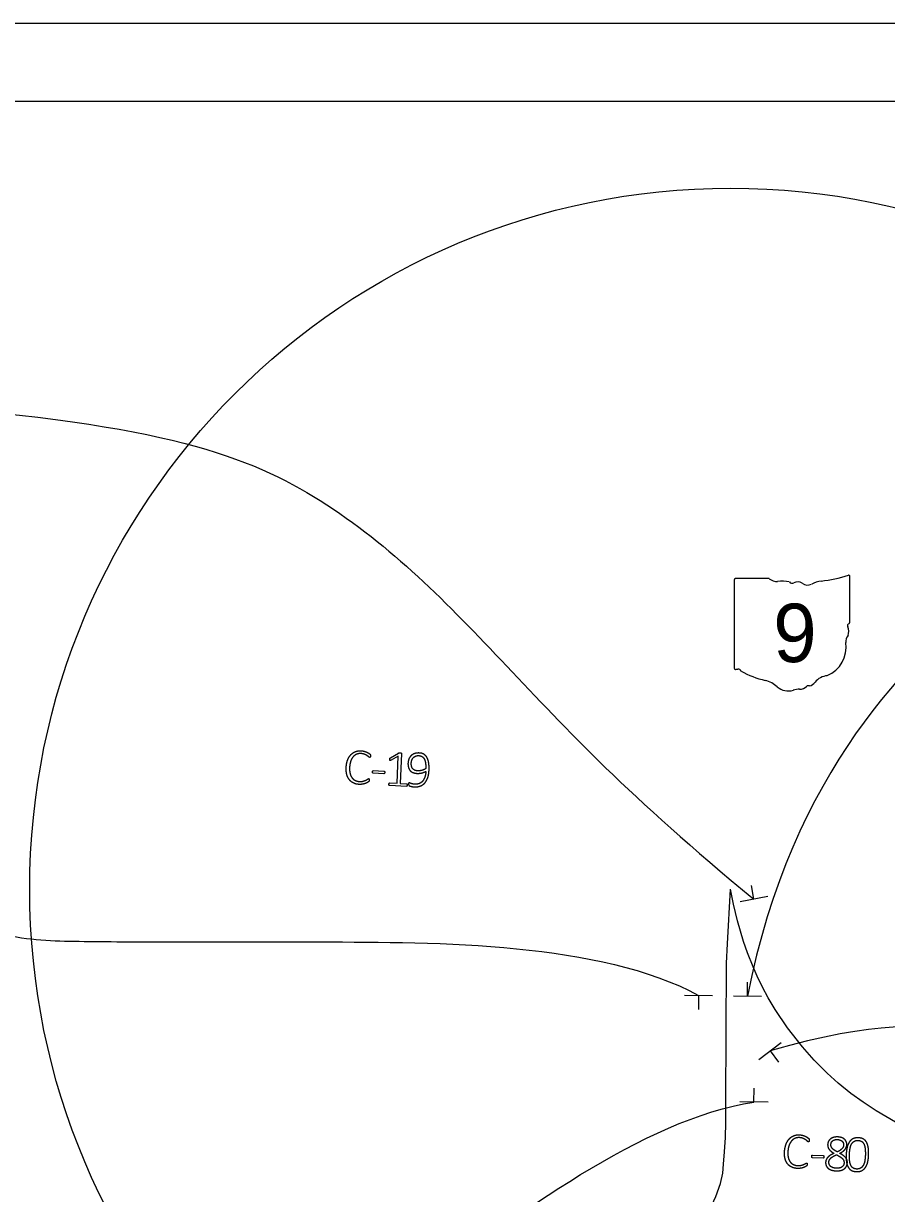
# Model space of a CAD drawing. Extents: x -202 to 1556, y 0 to 676.
# Drawn here: x 412.8 to 523.6, y 289.7 to 440 of the extents above; entities that cross this region are included whole.
import ezdxf

# ---------------------------------------------------------------- set-up
doc = ezdxf.new("R2010")
doc.units = 0
for name, color, linetype in [('Default', 7, 'Continuous'), ('GM_X_City_Street', 7, 'Continuous'), ('GM_X_Minor_Lake', 7, 'Continuous'), ('GM_X_State_Location', 7, 'Continuous'), ('SH_Border', 7, 'Continuous'), ('SH_Cut_Line', 7, 'Continuous'), ('SH_Data', 7, 'Continuous')]:
    doc.layers.add(name, color=color, linetype=linetype)

msp = doc.modelspace()

# ---------------------------------------------------------------- linework, layer by layer
at = {"layer": 'Default'}
for p, q in [((514.1, 294.69), (515.48, 294.62)), ((518.1, 295.99), (518.1, 295.99)), ((520.89, 294.67), (520.89, 294.67)), ((521.31, 294.69), (521.31, 294.69)), ((513.41, 293.48), (513.41, 293.48)), ((515.46, 294.3), (514.09, 294.36)), ((515.57, 294.46), (515.57, 294.46)), ((518.16, 293.69), (518.16, 293.69)), ((518.58, 293.73), (518.58, 293.73))]:
    msp.add_line(p, q, dxfattribs=at)
for points in [[(453.85, 253.83), (455.86, 255.51), (463.64, 260.9), (478.31, 270.7), (483.79, 274.45), (492.41, 280.21), (495.65, 282.4), (496.96, 283.36), (498.18, 284.37), (499.83, 286.07), (500.62, 287.27), (501.16, 288.25), (501.69, 289.38), (502.3, 291.03), (502.57, 292.38), (502.68, 293.54), (502.8, 295.12), (502.92, 296.94), (502.99, 298.87), (502.99, 301.52), (503.08, 319.32), (503.18, 321.83), (503.59, 328.84)], [(579.61, 280.65), (575.86, 281.89), (555.1, 288.55), (531.8, 295.84), (527.22, 297.75), (524.76, 298.93), (522.29, 300.36), (520.6, 301.48), (519.03, 302.61), (517.4, 303.94), (515.97, 305.23), (514.31, 306.9), (512.8, 308.58), (510.9, 311.04), (509.31, 313.39), (508.43, 314.89), (507.69, 316.25), (506.99, 317.65), (506.47, 318.86), (505.75, 320.66), (505.24, 322.11), (504.47, 324.76), (503.95, 326.92), (503.59, 328.84)]]:
    msp.add_lwpolyline(points, dxfattribs=at)
for points in [[(510.52, 295.25), (510.57, 295.76), (510.74, 296.16)], [(510.74, 296.16), (510.9, 296.56), (511.17, 296.82)], [(511.12, 296.01), (510.99, 295.68), (510.95, 295.23)], [(511.45, 296.55), (511.26, 296.34), (511.12, 296.01)], [(511.17, 296.82), (511.43, 297.09), (511.78, 297.21)], [(511.91, 296.86), (511.65, 296.77), (511.45, 296.55)], [(511.78, 297.21), (512.12, 297.33), (512.52, 297.29)], [(512.47, 296.93), (512.17, 296.96), (511.91, 296.86)], [(512.93, 296.82), (512.74, 296.9), (512.47, 296.93)], [(512.52, 297.29), (512.71, 297.27), (512.89, 297.22)], [(512.89, 297.22), (513.06, 297.17), (513.21, 297.1)], [(513.25, 296.64), (513.12, 296.73), (512.93, 296.82)], [(513.21, 297.1), (513.35, 297.03), (513.46, 296.94)], [(513.45, 296.47), (513.38, 296.54), (513.25, 296.64)], [(513.57, 296.39), (513.53, 296.39), (513.45, 296.47)], [(513.46, 296.94), (513.58, 296.86), (513.62, 296.81)], [(513.62, 296.4), (513.6, 296.39), (513.57, 296.39)], [(513.62, 296.81), (513.66, 296.76), (513.67, 296.74)], [(513.65, 296.43), (513.63, 296.41), (513.62, 296.4)], [(513.67, 296.49), (513.66, 296.46), (513.65, 296.43)], [(513.67, 296.74), (513.68, 296.72), (513.68, 296.7)], [(513.68, 296.57), (513.68, 296.53), (513.67, 296.49)], [(513.68, 296.7), (513.68, 296.67), (513.68, 296.64)], [(513.68, 296.64), (513.68, 296.61), (513.68, 296.57)], [(516.14, 296.43), (516.06, 296.25), (516.05, 296.04)], [(516.05, 296.04), (516.05, 295.87), (516.09, 295.71)], [(516.39, 296.75), (516.23, 296.61), (516.14, 296.43)], [(516.79, 296.96), (516.55, 296.89), (516.39, 296.75)], [(516.51, 295.79), (516.46, 295.91), (516.47, 296.05)], [(516.47, 296.05), (516.48, 296.36), (516.69, 296.53)], [(516.69, 296.53), (516.91, 296.7), (517.31, 296.69)], [(517.36, 297.02), (517.03, 297.03), (516.79, 296.96)], [(517.31, 296.69), (517.5, 296.68), (517.65, 296.62)], [(517.88, 296.92), (517.66, 297.01), (517.36, 297.02)], [(517.65, 296.62), (517.8, 296.57), (517.9, 296.48)], [(518.25, 296.7), (518.1, 296.83), (517.88, 296.92)], [(517.9, 296.48), (518.01, 296.39), (518.05, 296.27)], [(518.05, 296.27), (518.1, 296.14), (518.1, 295.99)], [(518.45, 296.38), (518.39, 296.56), (518.25, 296.7)], [(518.44, 295.68), (518.5, 295.84), (518.51, 296.02)], [(518.51, 296.02), (518.52, 296.21), (518.45, 296.38)], [(518.81, 296.34), (518.63, 296.06), (518.54, 295.66)], [(519.29, 296.78), (519, 296.63), (518.81, 296.34)], [(518.92, 295.48), (518.97, 295.8), (519.09, 296.05)], [(519.09, 296.05), (519.21, 296.3), (519.42, 296.44)], [(520, 296.91), (519.58, 296.93), (519.29, 296.78)], [(519.42, 296.44), (519.63, 296.59), (519.95, 296.57)], [(519.95, 296.57), (520.13, 296.57), (520.27, 296.51)], [(520.64, 296.75), (520.38, 296.9), (520, 296.91)], [(520.27, 296.51), (520.42, 296.46), (520.53, 296.36)], [(520.53, 296.36), (520.63, 296.25), (520.71, 296.1)], [(521.06, 296.32), (520.9, 296.6), (520.64, 296.75)], [(520.71, 296.1), (520.78, 295.94), (520.83, 295.73)], [(521.27, 295.63), (521.21, 296.03), (521.06, 296.32)], [(510.56, 294.34), (510.47, 294.75), (510.52, 295.25)], [(510.95, 295.23), (510.91, 294.81), (510.97, 294.48)], [(514, 294.53), (514, 294.62), (514.03, 294.66)], [(514.02, 294.4), (513.99, 294.44), (514, 294.53)], [(514.03, 294.66), (514.06, 294.69), (514.1, 294.69)], [(515.48, 294.62), (515.5, 294.62), (515.51, 294.61)], [(515.51, 294.61), (515.53, 294.6), (515.54, 294.58)], [(515.54, 294.58), (515.56, 294.56), (515.56, 294.53)], [(515.56, 294.53), (515.57, 294.5), (515.57, 294.46)], [(516.09, 295.71), (516.14, 295.56), (516.25, 295.42)], [(516.43, 294.7), (516.24, 294.58), (516.1, 294.44)], [(516.25, 295.42), (516.35, 295.28), (516.51, 295.16)], [(516.88, 294.92), (516.63, 294.81), (516.43, 294.7)], [(516.47, 294.32), (516.59, 294.43), (516.77, 294.53)], [(516.65, 295.55), (516.55, 295.67), (516.51, 295.79)], [(516.51, 295.16), (516.67, 295.03), (516.88, 294.92)], [(516.9, 295.33), (516.75, 295.44), (516.65, 295.55)], [(516.77, 294.53), (516.95, 294.64), (517.19, 294.74)], [(517.27, 295.1), (517.06, 295.22), (516.9, 295.33)], [(517.19, 294.74), (517.44, 294.61), (517.62, 294.49)], [(517.87, 295.49), (517.66, 295.27), (517.27, 295.1)], [(517.59, 294.92), (517.8, 295.02), (517.97, 295.14)], [(518.03, 294.66), (517.84, 294.79), (517.59, 294.92)], [(518.1, 295.99), (518.09, 295.71), (517.87, 295.49)], [(517.97, 295.14), (518.14, 295.25), (518.25, 295.39)], [(518.34, 294.38), (518.21, 294.53), (518.03, 294.66)], [(518.25, 295.39), (518.37, 295.53), (518.44, 295.68)], [(518.43, 294.79), (518.41, 294.26), (518.46, 293.85)], [(518.54, 295.66), (518.45, 295.26), (518.43, 294.79)], [(518.87, 293.97), (518.83, 294.32), (518.85, 294.81)], [(518.85, 294.81), (518.86, 295.16), (518.92, 295.48)], [(520.83, 295.73), (520.87, 295.52), (520.88, 295.26)], [(520.89, 294.67), (520.88, 294.44), (520.85, 294.21)], [(520.88, 295.26), (520.9, 294.99), (520.89, 294.67)], [(521.2, 293.81), (521.29, 294.21), (521.31, 294.69)], [(521.31, 294.69), (521.33, 295.22), (521.27, 295.63)], [(510.84, 293.65), (510.64, 293.94), (510.56, 294.34)], [(511.35, 293.19), (511.04, 293.36), (510.84, 293.65)], [(510.97, 294.48), (511.03, 294.14), (511.18, 293.9)], [(511.18, 293.9), (511.34, 293.66), (511.58, 293.52)], [(512.06, 292.98), (511.66, 293.02), (511.35, 293.19)], [(511.58, 293.52), (511.82, 293.38), (512.15, 293.35)], [(512.15, 293.35), (512.41, 293.33), (512.61, 293.37)], [(512.9, 293.07), (512.73, 293.02), (512.52, 292.99)], [(512.61, 293.37), (512.82, 293.42), (512.97, 293.49)], [(513.17, 293.19), (513.06, 293.13), (512.9, 293.07)], [(512.97, 293.49), (513.11, 293.56), (513.21, 293.62)], [(513.32, 293.28), (513.28, 293.25), (513.17, 293.19)], [(513.21, 293.62), (513.31, 293.67), (513.36, 293.67)], [(513.36, 293.32), (513.35, 293.3), (513.32, 293.28)], [(513.36, 293.67), (513.37, 293.67), (513.39, 293.66)], [(513.39, 293.36), (513.38, 293.34), (513.36, 293.32)], [(513.39, 293.66), (513.4, 293.65), (513.41, 293.63)], [(513.4, 293.42), (513.39, 293.39), (513.39, 293.36)], [(513.41, 293.48), (513.41, 293.44), (513.4, 293.42)], [(513.41, 293.63), (513.41, 293.61), (513.41, 293.57)], [(513.41, 293.57), (513.41, 293.53), (513.41, 293.48)], [(514.09, 294.36), (514.05, 294.36), (514.02, 294.4)], [(515.53, 294.33), (515.5, 294.29), (515.46, 294.3)], [(515.57, 294.46), (515.56, 294.36), (515.53, 294.33)], [(515.88, 294.14), (515.8, 293.97), (515.79, 293.76)], [(515.79, 293.76), (515.78, 293.51), (515.87, 293.31)], [(515.87, 293.31), (515.96, 293.12), (516.13, 292.98)], [(516.1, 294.44), (515.96, 294.31), (515.88, 294.14)], [(516.21, 293.79), (516.22, 293.95), (516.28, 294.08)], [(516.44, 293.23), (516.2, 293.44), (516.21, 293.79)], [(516.28, 294.08), (516.35, 294.2), (516.47, 294.32)], [(517.17, 293.01), (516.68, 293.03), (516.44, 293.23)], [(517.89, 293.17), (517.64, 292.99), (517.17, 293.01)], [(517.62, 294.49), (517.81, 294.37), (517.93, 294.25)], [(518.16, 293.69), (518.14, 293.36), (517.89, 293.17)], [(517.93, 294.25), (518.05, 294.13), (518.11, 293.99)], [(518.11, 293.99), (518.16, 293.86), (518.16, 293.69)], [(518.17, 292.92), (518.36, 293.05), (518.46, 293.26)], [(518.53, 294.08), (518.47, 294.24), (518.34, 294.38)], [(518.46, 293.85), (518.52, 293.44), (518.68, 293.16)], [(518.46, 293.26), (518.57, 293.46), (518.58, 293.73)], [(518.58, 293.73), (518.59, 293.92), (518.53, 294.08)], [(518.68, 293.16), (518.83, 292.88), (519.09, 292.73)], [(519.03, 293.38), (518.91, 293.61), (518.87, 293.97)], [(519.32, 293.03), (519.14, 293.15), (519.03, 293.38)], [(519.78, 292.9), (519.51, 292.92), (519.32, 293.03)], [(520.44, 293.14), (520.32, 293.02), (520.16, 292.96)], [(520.64, 293.43), (520.56, 293.26), (520.44, 293.14)], [(520.44, 292.7), (520.73, 292.85), (520.92, 293.13)], [(520.78, 293.79), (520.73, 293.6), (520.64, 293.43)], [(520.85, 294.21), (520.83, 293.99), (520.78, 293.79)], [(520.92, 293.13), (521.11, 293.42), (521.2, 293.81)], [(512.52, 292.99), (512.31, 292.96), (512.06, 292.98)], [(516.13, 292.98), (516.31, 292.84), (516.56, 292.76)], [(516.56, 292.76), (516.8, 292.69), (517.12, 292.67)], [(517.12, 292.67), (517.45, 292.66), (517.72, 292.72)], [(517.72, 292.72), (517.98, 292.78), (518.17, 292.92)], [(519.09, 292.73), (519.35, 292.58), (519.74, 292.57)], [(519.74, 292.57), (520.15, 292.55), (520.44, 292.7)], [(520.16, 292.96), (520, 292.9), (519.78, 292.9)]]:
    msp.add_open_spline(points, degree=2, dxfattribs=at)
at = {"layer": 'GM_X_City_Street'}
for p, q in [((504.06, 368.51), (504.06, 357.26)), ((508.55, 368.71), (504.21, 368.71)), ((518.89, 363.1), (518.89, 368.99)), ((518.89, 363.1), (518.89, 363.1))]:
    msp.add_line(p, q, dxfattribs=at)
for centre, radius, start, end in [((504.23, 368.54), 0.172, 98.1301, 188.1301), ((509.59, 370.01), 1.67, 231.6195, 271.1119), ((510.14, 362.39), 5.98, 80.4867, 94.9883), ((511.5, 368.6), 0.481, 219.7921, 297.1024), ((512.2, 367.3), 1, 54.4667, 119.1411), ((515.62, 365.27), 3.16, 97.3462, 120.7689), ((513.61, 384.05), 15.73, 275.8445, 288.9065), ((518.73, 369.01), 0.165, 351.8621, 97.738), ((513.49, 369.08), 1.2, 233.8562, 294.8282), ((518.85, 362.67), 0.256, 107.944, 210.337), ((517.23, 361.92), 1.53, 340.033, 23.6496), ((518.72, 363.08), 0.177, 289.6038, 7.7341), ((519.48, 360.63), 1.12, 136.8065, 186.9296), ((514.49, 359.89), 3.93, 292.3089, 8.9858), ((504.23, 357.23), 0.173, 171.9584, 258.3066), ((504.26, 358.38), 1.32, 267.339, 280.6039), ((504.53, 356.61), 0.477, 29.7484, 93.2717), ((510.55, 366.72), 11.36, 240.4129, 257.1985), ((516.15, 354.1), 2.15, 94.4031, 142.5768), ((507.17, 352.2), 3.55, 47.1842, 75.836), ((511.01, 356.55), 2.26, 230.7004, 286.2918), ((512.48, 355.71), 1.2, 268.777, 315.5493), ((513.56, 354.62), 0.338, 65.7517, 132.6484), ((513.42, 356.17), 1.27, 282.8732, 323.2771), ((512.31, 352.66), 1.85, 85.6951, 111.2099)]:
    msp.add_arc(centre, radius, start, end, dxfattribs=at)
at = {"layer": 'GM_X_Minor_Lake'}
for p, q in [((506.58, 327.55), (506.25, 329.32)), ((508.35, 327.88), (504.8, 327.23)), ((505.76, 315.08), (505.77, 316.88)), ((497.66, 315.21), (501.26, 315.19)), ((499.46, 315.2), (499.45, 313.4)), ((507.56, 315.07), (503.96, 315.09)), ((507.23, 306.95), (510.07, 309.16)), ((508.65, 308.06), (509.75, 306.63)), ((506.59, 301.5), (506.6, 303.3)), ((508.39, 301.49), (504.79, 301.51))]:
    msp.add_line(p, q, dxfattribs=at)
at = {"layer": 'GM_X_State_Location'}
for p, q in [((459.91, 345.72), (460.96, 346.32)), ((464.45, 344.32), (464.45, 344.32)), ((464.87, 344.28), (464.87, 344.28)), ((457.19, 342.84), (457.19, 342.84)), ((459.06, 343.66), (457.69, 343.73)), ((457.71, 344.06), (459.08, 343.99)), ((459.17, 343.82), (459.17, 343.82)), ((461.95, 342.04), (459.81, 342.13)), ((462.07, 342.2), (462.07, 342.2))]:
    msp.add_line(p, q, dxfattribs=at)
for points in [[(459.82, 342.47), (460.76, 342.43), (460.91, 345.9), (459.99, 345.39)], [(461.33, 346.25), (461.16, 342.41), (461.97, 342.37)]]:
    msp.add_lwpolyline(points, dxfattribs=at)
for points in [[(454.41, 345.41), (454.56, 345.82), (454.82, 346.09)], [(455.12, 345.83), (454.92, 345.61), (454.81, 345.27)], [(454.82, 346.09), (455.07, 346.36), (455.41, 346.5)], [(455.56, 346.16), (455.31, 346.05), (455.12, 345.83)], [(455.41, 346.5), (455.75, 346.63), (456.15, 346.61)], [(456.11, 346.25), (455.82, 346.26), (455.56, 346.16)], [(456.58, 346.15), (456.39, 346.23), (456.11, 346.25)], [(456.15, 346.61), (456.34, 346.6), (456.52, 346.55)], [(456.52, 346.55), (456.7, 346.51), (456.84, 346.44)], [(456.9, 345.99), (456.77, 346.08), (456.58, 346.15)], [(456.84, 346.44), (456.99, 346.38), (457.11, 346.3)], [(457.11, 345.83), (457.03, 345.9), (456.9, 345.99)], [(457.11, 346.3), (457.22, 346.22), (457.26, 346.18)], [(457.24, 345.75), (457.19, 345.76), (457.11, 345.83)], [(457.28, 345.76), (457.26, 345.75), (457.24, 345.75)], [(457.26, 346.18), (457.31, 346.13), (457.32, 346.11)], [(457.31, 345.8), (457.3, 345.78), (457.28, 345.76)], [(457.33, 345.86), (457.32, 345.82), (457.31, 345.8)], [(457.32, 346.11), (457.33, 346.09), (457.33, 346.06)], [(457.33, 346.06), (457.34, 346.04), (457.34, 346.01)], [(457.34, 345.94), (457.34, 345.89), (457.33, 345.86)], [(457.34, 346.01), (457.34, 345.98), (457.34, 345.94)], [(459.83, 345.59), (459.84, 345.62), (459.85, 345.65)], [(459.83, 345.52), (459.83, 345.56), (459.83, 345.59)], [(459.85, 345.65), (459.86, 345.67), (459.87, 345.69)], [(459.87, 345.69), (459.89, 345.7), (459.91, 345.72)], [(460.96, 346.32), (460.97, 346.33), (460.98, 346.33)], [(460.98, 346.33), (461, 346.34), (461.02, 346.34)], [(461.02, 346.34), (461.05, 346.35), (461.07, 346.35)], [(461.07, 346.35), (461.1, 346.35), (461.14, 346.35)], [(461.14, 346.35), (461.19, 346.34), (461.23, 346.33)], [(461.23, 346.33), (461.27, 346.33), (461.29, 346.32)], [(461.29, 346.32), (461.32, 346.31), (461.32, 346.29)], [(461.32, 346.29), (461.33, 346.27), (461.33, 346.25)], [(462.49, 345.9), (462.32, 345.71), (462.25, 345.47)], [(462.92, 346.21), (462.66, 346.1), (462.49, 345.9)], [(462.64, 345.34), (462.69, 345.52), (462.8, 345.67)], [(462.8, 345.67), (462.92, 345.81), (463.09, 345.9)], [(463.57, 346.32), (463.19, 346.33), (462.92, 346.21)], [(463.09, 345.9), (463.26, 345.99), (463.51, 345.99)], [(463.51, 345.99), (463.74, 345.98), (463.92, 345.89)], [(464.01, 346.25), (463.82, 346.32), (463.57, 346.32)], [(463.92, 345.89), (464.1, 345.8), (464.22, 345.6)], [(464.35, 346.05), (464.2, 346.18), (464.01, 346.25)], [(464.22, 345.6), (464.34, 345.41), (464.4, 345.09)], [(464.6, 345.75), (464.5, 345.93), (464.35, 346.05)], [(464.76, 345.34), (464.7, 345.57), (464.6, 345.75)], [(454.3, 343.59), (454.2, 343.99), (454.23, 344.49)], [(454.23, 344.49), (454.26, 345.01), (454.41, 345.41)], [(454.81, 345.27), (454.69, 344.94), (454.66, 344.49)], [(454.66, 344.49), (454.64, 344.07), (454.71, 343.74)], [(459.83, 345.43), (459.82, 345.47), (459.83, 345.52)], [(459.85, 345.37), (459.83, 345.39), (459.83, 345.43)], [(459.91, 345.36), (459.87, 345.36), (459.85, 345.37)], [(459.99, 345.39), (459.94, 345.36), (459.91, 345.36)], [(462.25, 345.47), (462.17, 345.22), (462.16, 344.96)], [(462.16, 344.96), (462.16, 344.7), (462.22, 344.48)], [(462.22, 344.48), (462.28, 344.25), (462.42, 344.08)], [(462.42, 344.08), (462.56, 343.91), (462.81, 343.81)], [(462.58, 344.99), (462.59, 345.16), (462.64, 345.34)], [(462.63, 344.6), (462.58, 344.78), (462.58, 344.99)], [(462.77, 344.3), (462.67, 344.43), (462.63, 344.6)], [(463.05, 344.1), (462.88, 344.18), (462.77, 344.3)], [(463.46, 344.03), (463.21, 344.03), (463.05, 344.1)], [(464, 344.1), (463.74, 344.03), (463.46, 344.03)], [(464.45, 344.32), (464.26, 344.18), (464, 344.1)], [(464.4, 345.09), (464.46, 344.77), (464.45, 344.32)], [(464.85, 344.85), (464.82, 345.11), (464.76, 345.34)], [(464.83, 343.71), (464.87, 344), (464.87, 344.28)], [(464.87, 344.28), (464.88, 344.58), (464.85, 344.85)], [(454.62, 342.91), (454.4, 343.19), (454.3, 343.59)], [(455.15, 342.47), (454.83, 342.63), (454.62, 342.91)], [(454.71, 343.74), (454.79, 343.41), (454.95, 343.17)], [(454.95, 343.17), (455.11, 342.94), (455.36, 342.81)], [(455.36, 342.81), (455.61, 342.68), (455.93, 342.66)], [(455.93, 342.66), (456.2, 342.64), (456.4, 342.7)], [(456.4, 342.7), (456.6, 342.76), (456.74, 342.83)], [(456.74, 342.83), (456.89, 342.9), (456.98, 342.97)], [(457.1, 342.63), (457.07, 342.6), (456.96, 342.54)], [(456.98, 342.97), (457.08, 343.03), (457.13, 343.03)], [(457.15, 342.68), (457.14, 342.66), (457.1, 342.63)], [(457.13, 343.03), (457.15, 343.02), (457.16, 343.02)], [(457.17, 342.72), (457.16, 342.7), (457.15, 342.68)], [(457.16, 343.02), (457.17, 343.01), (457.18, 342.99)], [(457.18, 342.77), (457.18, 342.74), (457.17, 342.72)], [(457.18, 342.99), (457.19, 342.96), (457.19, 342.93)], [(457.19, 342.84), (457.19, 342.8), (457.18, 342.77)], [(457.19, 342.93), (457.19, 342.89), (457.19, 342.84)], [(457.6, 343.9), (457.61, 343.99), (457.64, 344.03)], [(457.62, 343.77), (457.6, 343.81), (457.6, 343.9)], [(457.69, 343.73), (457.65, 343.74), (457.62, 343.77)], [(457.64, 344.03), (457.67, 344.06), (457.71, 344.06)], [(459.14, 343.69), (459.11, 343.66), (459.06, 343.66)], [(459.08, 343.99), (459.1, 343.99), (459.12, 343.98)], [(459.12, 343.98), (459.14, 343.97), (459.15, 343.95)], [(459.17, 343.82), (459.16, 343.72), (459.14, 343.69)], [(459.15, 343.95), (459.16, 343.93), (459.17, 343.9)], [(459.17, 343.9), (459.17, 343.87), (459.17, 343.82)], [(462.81, 343.81), (463.05, 343.71), (463.41, 343.7)], [(463.41, 343.7), (463.75, 343.7), (464.01, 343.78)], [(464.11, 342.8), (463.95, 342.57), (463.7, 342.44)], [(464.01, 343.78), (464.27, 343.86), (464.46, 343.96)], [(464.36, 343.33), (464.27, 343.03), (464.11, 342.8)], [(464.15, 342.31), (464.35, 342.47), (464.48, 342.69)], [(464.46, 343.96), (464.44, 343.63), (464.36, 343.33)], [(464.48, 342.69), (464.62, 342.92), (464.71, 343.17)], [(464.71, 343.17), (464.79, 343.43), (464.83, 343.71)], [(455.86, 342.29), (455.46, 342.31), (455.15, 342.47)], [(456.32, 342.31), (456.11, 342.28), (455.86, 342.29)], [(456.69, 342.41), (456.53, 342.35), (456.32, 342.31)], [(456.96, 342.54), (456.85, 342.47), (456.69, 342.41)], [(459.71, 342.3), (459.71, 342.34), (459.72, 342.37)], [(459.71, 342.22), (459.7, 342.25), (459.71, 342.3)], [(459.74, 342.17), (459.72, 342.19), (459.71, 342.22)], [(459.72, 342.37), (459.73, 342.4), (459.74, 342.43)], [(459.74, 342.43), (459.76, 342.45), (459.78, 342.46)], [(459.77, 342.14), (459.75, 342.15), (459.74, 342.17)], [(459.81, 342.13), (459.79, 342.13), (459.77, 342.14)], [(459.78, 342.46), (459.8, 342.47), (459.82, 342.47)], [(461.99, 342.04), (461.97, 342.04), (461.95, 342.04)], [(461.97, 342.37), (461.99, 342.37), (462.01, 342.36)], [(462.03, 342.07), (462.01, 342.05), (461.99, 342.04)], [(462.01, 342.36), (462.03, 342.35), (462.05, 342.32)], [(462.06, 342.12), (462.05, 342.09), (462.03, 342.07)], [(462.05, 342.32), (462.06, 342.3), (462.07, 342.27)], [(462.07, 342.2), (462.07, 342.15), (462.06, 342.12)], [(462.07, 342.27), (462.07, 342.24), (462.07, 342.2)], [(462.24, 342.41), (462.23, 342.38), (462.23, 342.33)], [(462.23, 342.33), (462.23, 342.26), (462.25, 342.22)], [(462.25, 342.46), (462.24, 342.44), (462.24, 342.41)], [(462.28, 342.48), (462.26, 342.47), (462.25, 342.46)], [(462.25, 342.22), (462.26, 342.18), (462.29, 342.15)], [(462.31, 342.49), (462.29, 342.49), (462.28, 342.48)], [(462.29, 342.15), (462.32, 342.12), (462.39, 342.09)], [(462.41, 342.46), (462.35, 342.49), (462.31, 342.49)], [(462.39, 342.09), (462.45, 342.07), (462.55, 342.04)], [(462.57, 342.4), (462.47, 342.43), (462.41, 342.46)], [(462.55, 342.04), (462.65, 342.01), (462.78, 341.99)], [(462.8, 342.34), (462.67, 342.37), (462.57, 342.4)], [(462.78, 341.99), (462.91, 341.98), (463.06, 341.97)], [(463.11, 342.31), (462.94, 342.32), (462.8, 342.34)], [(463.06, 341.97), (463.41, 341.97), (463.68, 342.06)], [(463.7, 342.44), (463.45, 342.31), (463.11, 342.31)], [(463.68, 342.06), (463.95, 342.15), (464.15, 342.31)]]:
    msp.add_open_spline(points, degree=2, dxfattribs=at)
at = {"layer": 'SH_Border'}
msp.add_lwpolyline([(30, 430), (670, 430), (670, 10), (30, 10)], close=True, dxfattribs=at)
at = {"layer": 'SH_Cut_Line'}
msp.add_lwpolyline([(0, 0), (680, 0), (680, 440), (0, 440)], close=True, dxfattribs=at)
at = {"layer": 'SH_Data'}
msp.add_circle((503.59, 328.84), 90, dxfattribs=at)
for points in [[(398.73, 390.94), (430.7, 388.56), (452.83, 380.39), (474.4, 358.12), (490.52, 340.72), (506.58, 327.55)], [(595.23, 387.79), (576.58, 388.37), (559.82, 383.23), (541.84, 372.9), (511.42, 344.06), (505.76, 315.08)], [(393.64, 328.39), (408.52, 322.46), (417.67, 322.03), (444.96, 322.07), (486.87, 322.04), (499.46, 315.2)], [(594.07, 296.86), (581.34, 305.55), (544.58, 308.38), (535.1, 310.52), (522.4, 312.09), (508.65, 308.06)], [(404.64, 246.73), (424.34, 248.87), (437.23, 257.61), (458.97, 274.11), (492.42, 299.36), (506.59, 301.5)]]:
    msp.add_open_spline(points, degree=3, dxfattribs=at)

# ---------------------------------------------------------------- texts
at = {"layer": 'GM_X_City_Street'}
msp.add_text('9', height=7.5, dxfattribs=at).set_placement((509.06, 357.99))

doc.saveas('drawing.dxf')
